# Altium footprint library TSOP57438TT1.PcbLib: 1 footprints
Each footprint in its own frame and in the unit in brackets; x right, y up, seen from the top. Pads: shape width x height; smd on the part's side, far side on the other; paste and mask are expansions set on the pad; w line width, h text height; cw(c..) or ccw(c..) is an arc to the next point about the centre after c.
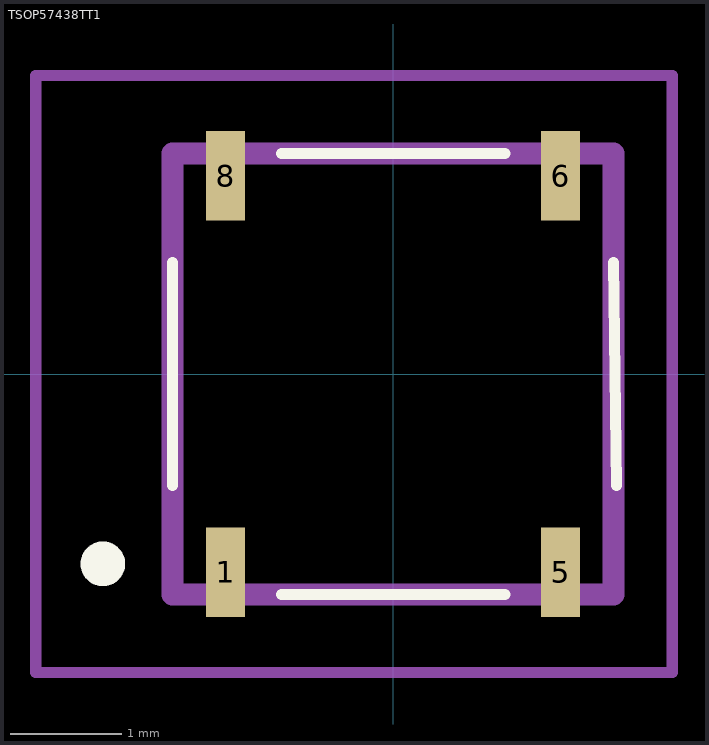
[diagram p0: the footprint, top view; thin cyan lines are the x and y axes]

## TSOP57438TT1 [mm]
pads (4):
  rect 0.35x0.8 smd: 1(-1.5,-1.775) 5(1.5,-1.775) 6(1.5,1.775) 8(-1.5,1.775)
Top Overlay:
  lines w0.1: -1.975,-1 -1.975,1 ; -1,-1.975 1,-1.975 ; -1,1.975 1,1.975 ; 1.975,1 2,-1
  lines w0.2: -2.6,-1.8 ccw(c-2.6,-1.7) -2.6,-1.6 ; -2.6,-1.8 -2.6,-1.8 ; -2.6,-1.8 cw(c-2.6,-1.7) -2.6,-1.6 ; -2.6,-1.6 -2.6,-1.6
Mechanical 15:
  lines w0.2: -1.975,-1.975 1.975,-1.975 1.975,1.975 -1.975,1.975 -1.975,-1.975
Mechanical 20:
  lines w0.1: -3.2,-2.675 2.5,-2.675 2.5,2.675 -3.2,2.675 -3.2,-2.675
